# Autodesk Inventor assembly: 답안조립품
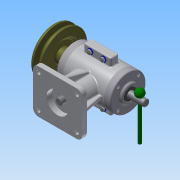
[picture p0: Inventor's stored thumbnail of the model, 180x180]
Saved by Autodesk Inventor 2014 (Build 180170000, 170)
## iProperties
Created: 2015-12
Part Number: 답안조립품
Document SubType Name: Assembly
Designer: imci
Author: imci
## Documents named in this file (19)
- C:\Users\imci\Desktop\351208V1040\답안조립품.iam
- C:\Users\imci\Desktop\351208V1040\본체.ipt
- C:\Users\imci\Desktop\351208V1040\V-벨트풀리.ipt
- C:\Users\imci\Desktop\351208V1040\너트 M4.ipt
- C:\Users\imci\Desktop\351208V1040\뒤커버.ipt
- C:\Users\imci\Desktop\351208V1040\레바.ipt
- C:\Users\imci\Desktop\351208V1040\멈춤나사 M3x8.ipt
- C:\Users\imci\Desktop\351208V1040\베어링 6201.ipt
- C:\Users\imci\Desktop\351208V1040\베어링 6202.ipt
- C:\Users\imci\Desktop\351208V1040\본체커버.ipt
- C:\Users\imci\Desktop\351208V1040\볼트 M3x0.5x8.ipt
- C:\Users\imci\Desktop\351208V1040\볼트 M4 x 16.ipt
- C:\Users\imci\Desktop\351208V1040\스프링.ipt
- C:\Users\imci\Desktop\351208V1040\슬라이드.ipt
- C:\Users\imci\Desktop\351208V1040\앞커버.ipt
- C:\Users\imci\Desktop\351208V1040\오일실 12 22 7.ipt
- C:\Users\imci\Desktop\351208V1040\와셔 ST 4-100.ipt
- C:\Users\imci\Desktop\351208V1040\키 4 x 4 x 18.ipt
- C:\Users\imci\Desktop\351208V1040\편심축.ipt
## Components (13 placed, 4 different names)
1. V-벨트풀리:1
2. ISO 4032 M4:1
3. ISO 4762 M4 x 16:1
4. ISO 7091 ST 4 - 100 HV:1
5. ISO 4032 M4:2
6. ISO 4762 M4 x 16:2
7. ISO 7091 ST 4 - 100 HV:2
8. ISO 4032 M4:3
9. ISO 4762 M4 x 16:3
10. ISO 7091 ST 4 - 100 HV:3
11. ISO 4032 M4:4
12. ISO 4762 M4 x 16:4
13. ISO 7091 ST 4 - 100 HV:4
